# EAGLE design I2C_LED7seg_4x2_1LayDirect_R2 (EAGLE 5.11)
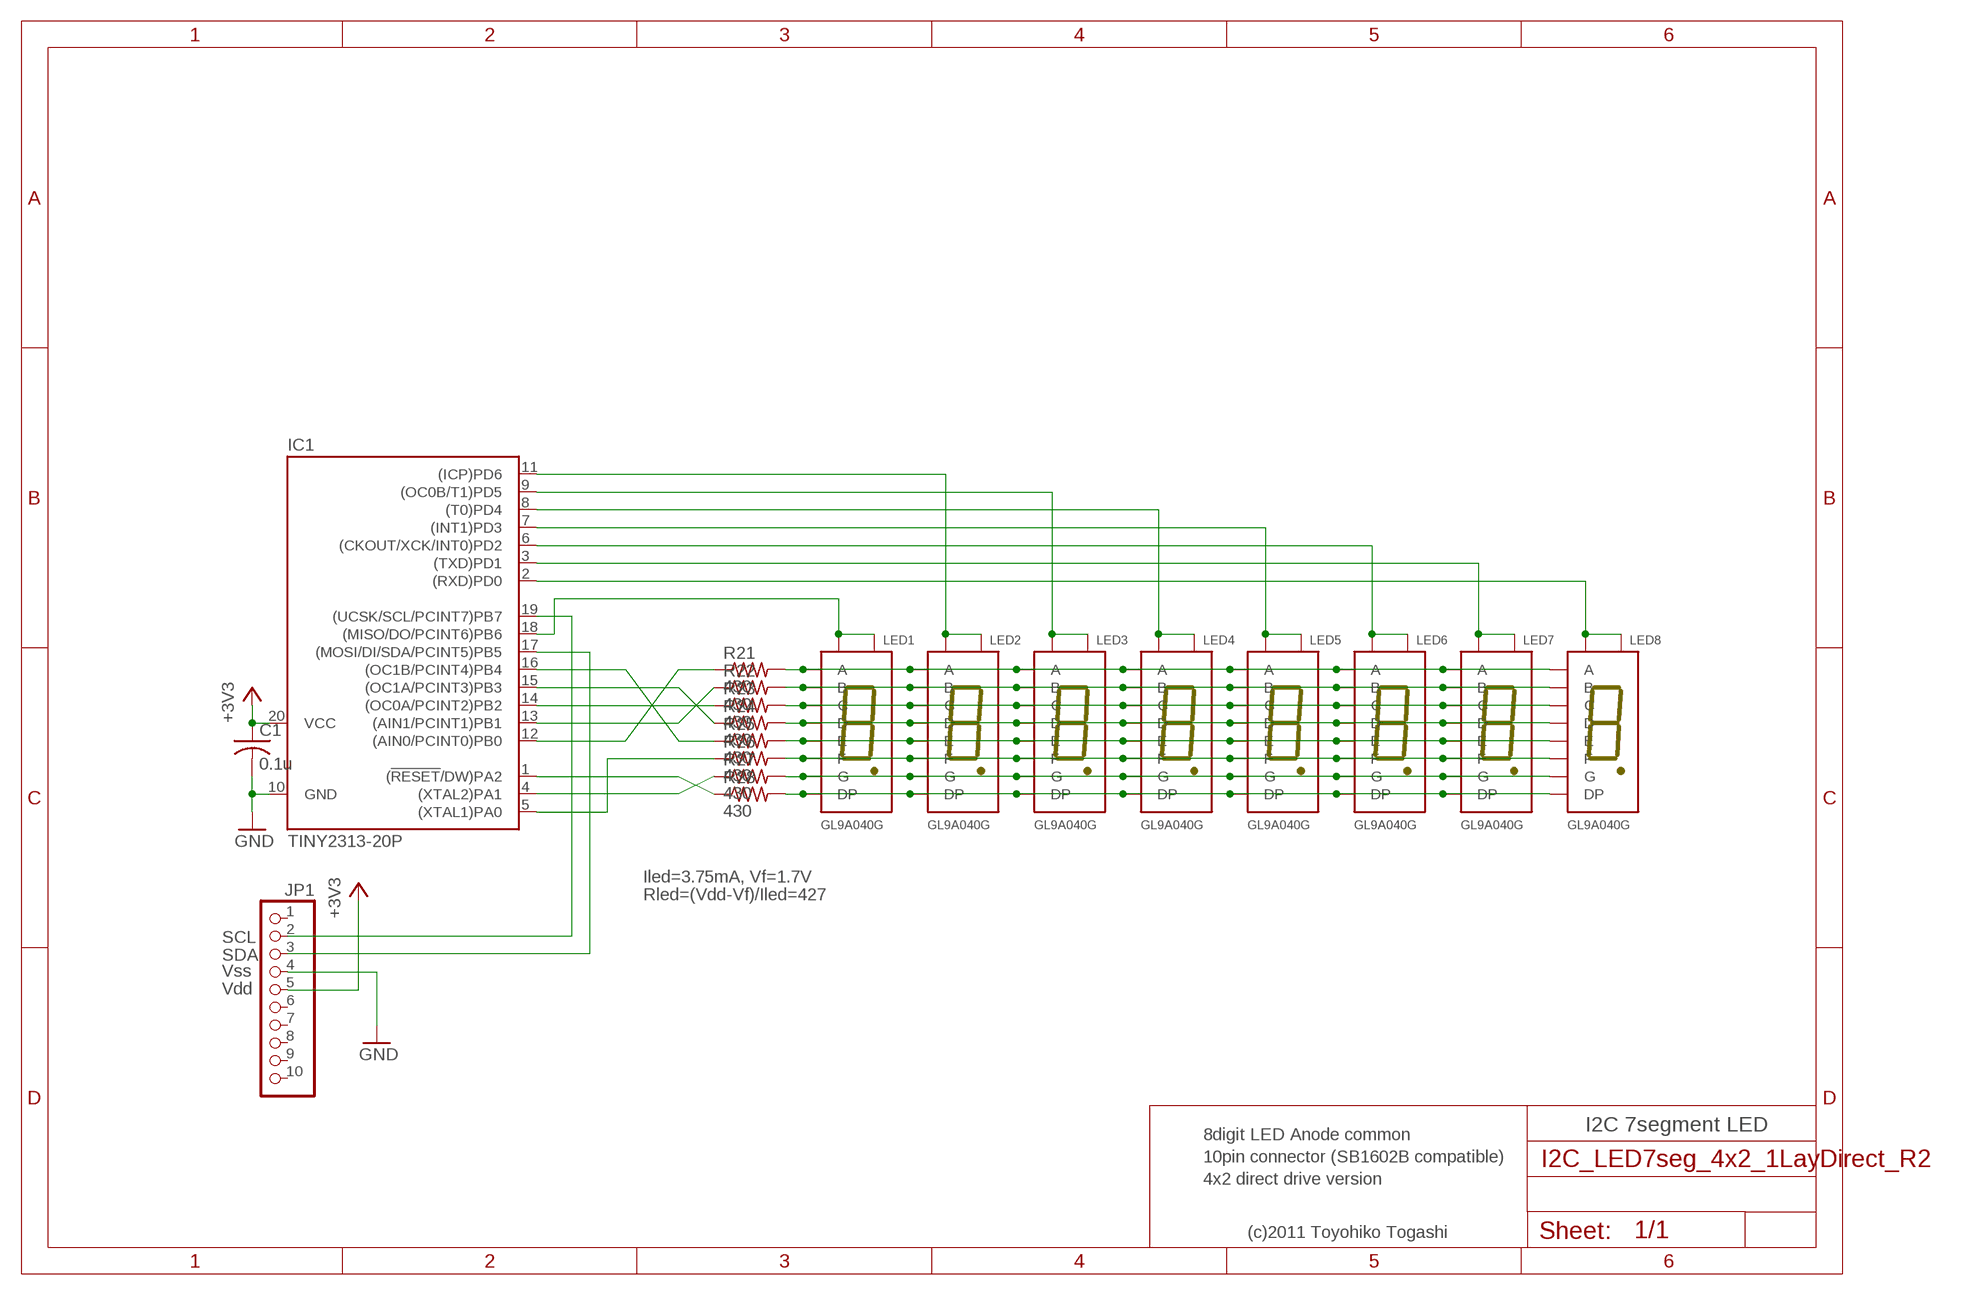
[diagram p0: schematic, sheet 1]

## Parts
C1  0.1u  C-US025-024X044  [C025-024X044]
IC1  TINY2313-20P  [DIL20]
JP1  PINHD-1X10  [1X10]
LED1  GL9A040G  [GL9A040G]
LED2  GL9A040G  [GL9A040G]
LED3  GL9A040G  [GL9A040G]
LED4  GL9A040G  [GL9A040G]
LED5  GL9A040G  [GL9A040G]
LED6  GL9A040G  [GL9A040G]
LED7  GL9A040G  [GL9A040G]
LED8  GL9A040G  [GL9A040G]
R21  430  R-US_0204/2V  [0204V]
R22  430  R-US_0204/2V  [0204V]
R23  430  R-US_0204/2V  [0204V]
R24  430  R-US_0204/2V  [0204V]
R25  430  R-US_0204/2V  [0204V]
R26  430  R-US_0204/5  [0204/5]
R27  430  R-US_0204/5  [0204/5]
R28  430  R-US_0204/5  [0204/5]

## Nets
+3V3: C1.1 IC1.20(VCC) JP1.5
GND: C1.2 IC1.10(GND) JP1.4
N$1: LED1.P$3(G) LED2.P$3(G) LED3.P$3(G) LED4.P$3(G) LED5.P$3(G) LED6.P$3(G) LED7.P$3(G) LED8.P$3(G) R27.2
N$2: LED1.P$7(DP) LED2.P$7(DP) LED3.P$7(DP) LED4.P$7(DP) LED5.P$7(DP) LED6.P$7(DP) LED7.P$7(DP) LED8.P$7(DP) R28.2
N$3: IC1.19((UCSK/SCL/PCINT7)PB7) JP1.2
N$4: IC1.17((MOSI/DI/SDA/PCINT5)PB5) JP1.3
N$5: LED1.P$10(A) LED2.P$10(A) LED3.P$10(A) LED4.P$10(A) LED5.P$10(A) LED6.P$10(A) LED7.P$10(A) LED8.P$10(A) R21.2
N$7: LED1.P$8(C) LED2.P$8(C) LED3.P$8(C) LED4.P$8(C) LED5.P$8(C) LED6.P$8(C) LED7.P$8(C) LED8.P$8(C) R23.2
N$8: LED1.P$5(D) LED2.P$5(D) LED3.P$5(D) LED4.P$5(D) LED5.P$5(D) LED6.P$5(D) LED7.P$5(D) LED8.P$5(D) R24.2
N$14: IC1.5((XTAL1)PA0) R26.1
N$15: IC1.4((XTAL2)PA1) R27.1
N$16: IC1.1((!RESET!/DW)PA2) R28.1
N$17: IC1.12((AIN0/PCINT0)PB0) R21.1
N$19: IC1.13((AIN1/PCINT1)PB1) R22.1
N$20: IC1.14((OC0A/PCINT2)PB2) R23.1
N$21: IC1.15((OC1A/PCINT3)PB3) R24.1
N$22: IC1.16((OC1B/PCINT4)PB4) R25.1
N$25: IC1.18((MISO/DO/PCINT6)PB6) LED1.P$1(CA1) LED1.P$6(CA6)
N$28: IC1.2((RXD)PD0) LED8.P$1(CA1) LED8.P$6(CA6)
N$41: LED1.P$9(B) LED2.P$9(B) LED3.P$9(B) LED4.P$9(B) LED5.P$9(B) LED6.P$9(B) LED7.P$9(B) LED8.P$9(B) R22.2
N$44: LED1.P$4(E) LED2.P$4(E) LED3.P$4(E) LED4.P$4(E) LED5.P$4(E) LED6.P$4(E) LED7.P$4(E) LED8.P$4(E) R25.2
N$45: LED1.P$2(F) LED2.P$2(F) LED3.P$2(F) LED4.P$2(F) LED5.P$2(F) LED6.P$2(F) LED7.P$2(F) LED8.P$2(F) R26.2
N$50: IC1.3((TXD)PD1) LED7.P$1(CA1) LED7.P$6(CA6)
N$53: IC1.7((INT1)PD3) LED5.P$1(CA1) LED5.P$6(CA6)
N$54: IC1.9((OC0B/T1)PD5) LED3.P$1(CA1) LED3.P$6(CA6)
N$98: IC1.11((ICP)PD6) LED2.P$1(CA1) LED2.P$6(CA6)
N$100: IC1.8((T0)PD4) LED4.P$1(CA1) LED4.P$6(CA6)
N$102: IC1.6((CKOUT/XCK/INT0)PD2) LED6.P$1(CA1) LED6.P$6(CA6)
Unconnected: JP1.1 JP1.6 JP1.7 JP1.8 JP1.9 JP1.10

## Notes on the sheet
- Iled=3.75mA, Vf=1.7V
- Rled=(Vdd-Vf)/Iled=427
- SCL
- SDA
- Vss
- Vdd
- I2C 7segment LED
- 8digit LED Anode common
- 10pin connector (SB1602B compatible)
- 4x2 direct drive version
- (c)2011 Toyohiko Togashi

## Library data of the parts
C1 = rcl:C-US: CAPACITOR, American symbol
IC1 = TOG:TINY2313: 8-bit AVR Microcontroller with 2K Bytes Flash Source: http://www.atmel.com .. doc2543.pdf
JP1 = pinhead:PINHD-1X10: PIN HEADER
LED1-LED8 = TOG:GL9A040G: 7 Segment LED
R21-R28 = rcl:R-US_: RESISTOR, American symbol

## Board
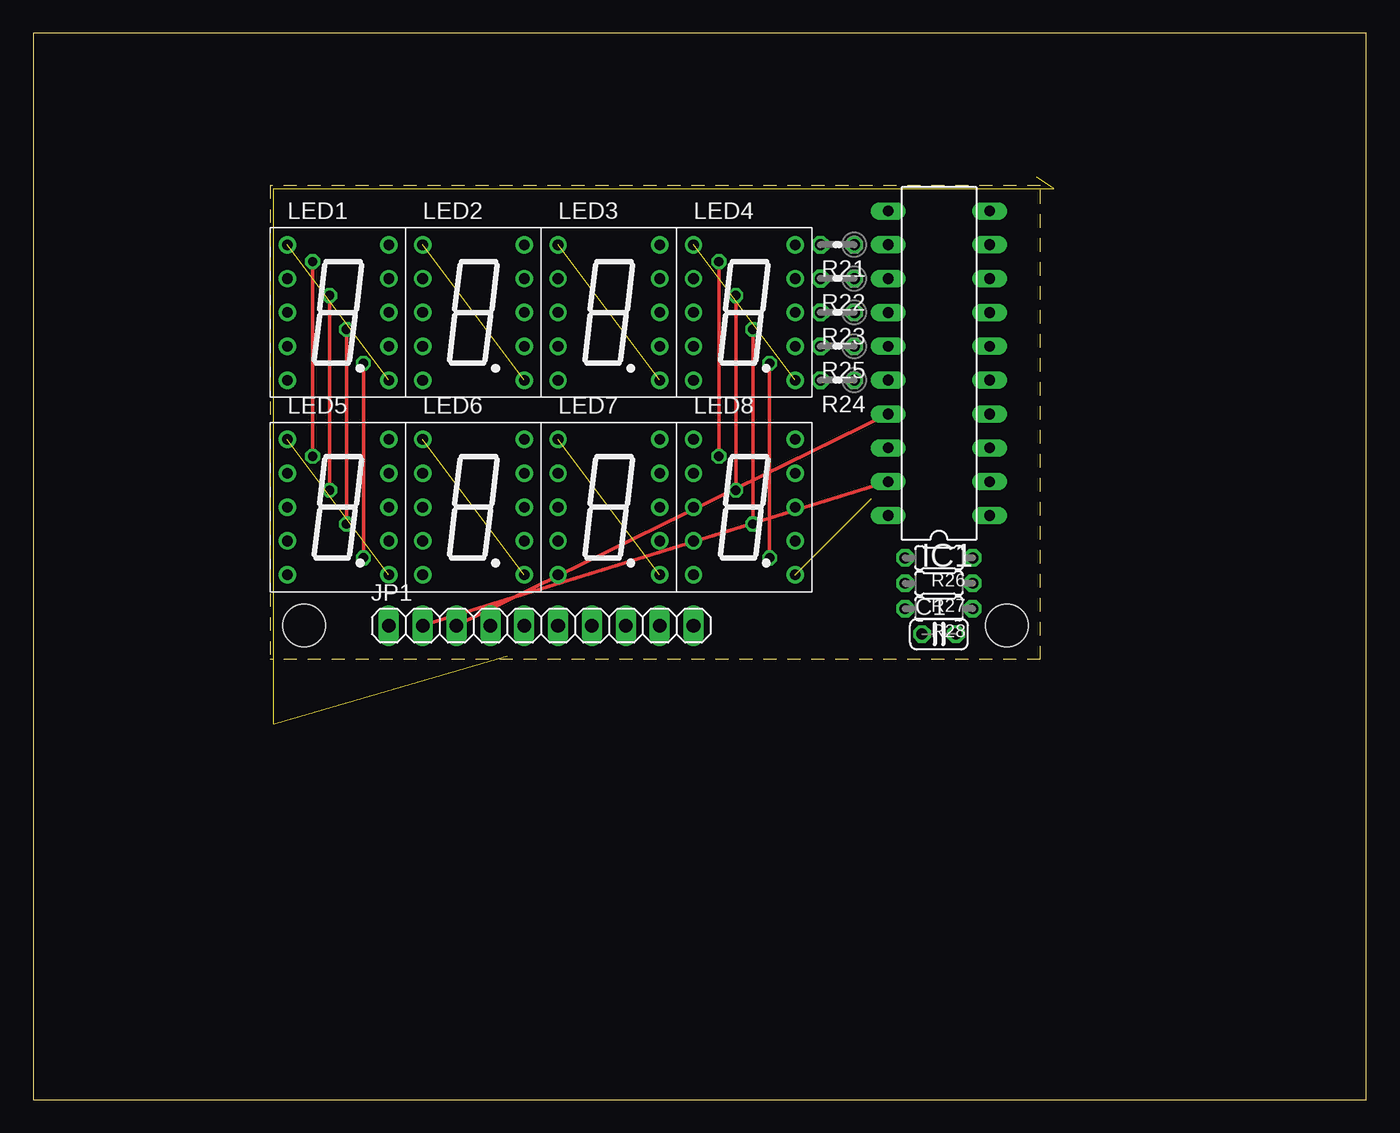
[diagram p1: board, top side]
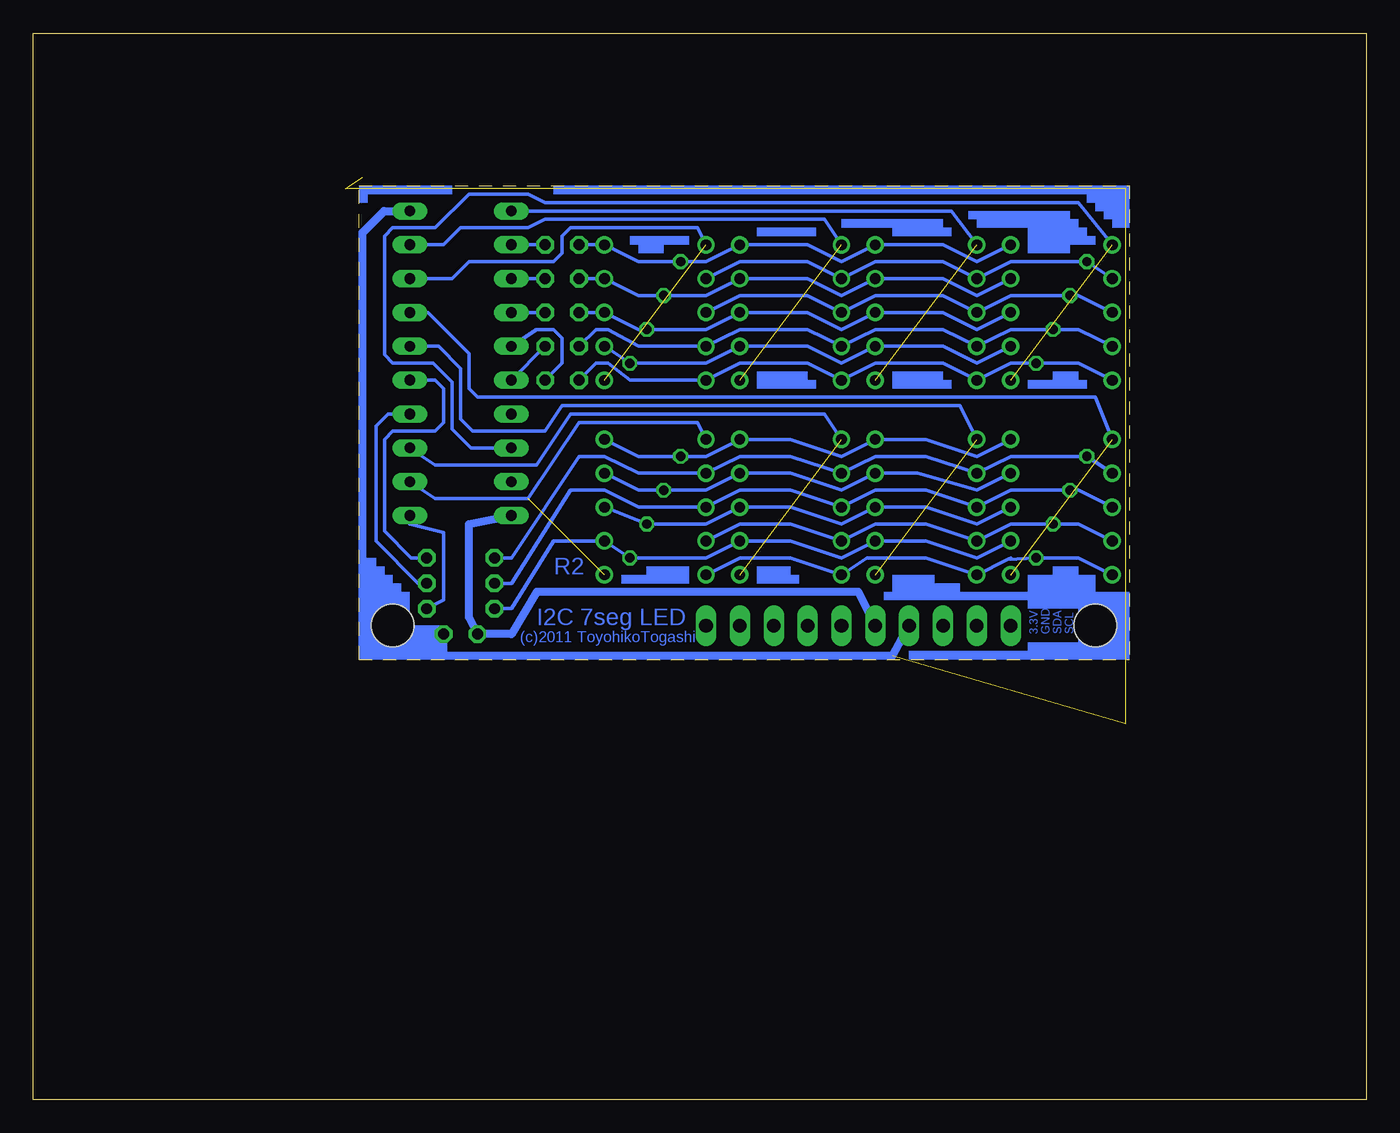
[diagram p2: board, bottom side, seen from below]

Size 100 x 80 mm. Coordinates in mm from the lower left corner, seen from the top.
Outline: 0,0 100,0 100,80 0,80 0,0
Outline: 17.78,68.58 17.78,33.02 75.56,33.02 75.56,68.58 17.78,68.58
Copper layers (1*16): Top 0.035mm / dielectric 1.5mm / Bottom 0.035mm
Design rules "default": minimum track width 10mil, minimum drill 24mil, track to track 8mil, track to pad 8mil, pad to pad 8mil, via to via 8mil, smd to smd 8mil, copper to edge 40mil, drill to drill 8mil, minimum pad ring 10mil, minimum via ring 8mil, stop-mask expansion 4mil, vias tented up to drill 0mil, thermal gap 10mil
Holes 3.2 mm at 73.03,35.56 20.32,35.56

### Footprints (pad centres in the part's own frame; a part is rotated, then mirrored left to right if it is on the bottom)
C025-024X044 = drill 0.813 octagon: 1 -1.27,0; 2 1.27,0
DIL20@1 = drill 0.813 long: 1 -11.43,-3.81; 2 -8.89,-3.81; 3 -6.35,-3.81; 4 -3.81,-3.81; 5 -1.27,-3.81; 6 1.27,-3.81; 7 3.81,-3.81; 8 6.35,-3.81; 9 8.89,-3.81; 10 11.43,-3.81; 11 11.43,3.81; 12 8.89,3.81; 13 6.35,3.81; 14 3.81,3.81; 15 1.27,3.81; 16 -1.27,3.81; 17 -3.81,3.81; 18 -6.35,3.81; 19 -8.89,3.81; 20 -11.43,3.81
1X10 = drill 1.016 long: 1 -11.43,0; 2 -8.89,0; 3 -6.35,0; 4 -3.81,0; 5 -1.27,0; 6 1.27,0; 7 3.81,0; 8 6.35,0; 9 8.89,0; 10 11.43,0
GL9A040G = drill 0.8 round: P$1 -3.81,5.08; P$2 -3.81,2.54; P$3 -3.81,0; P$4 -3.81,-2.54; P$5 -3.81,-5.08; P$6 3.81,-5.08; P$7 3.81,-2.54; P$8 3.81,0; P$9 3.81,2.54; P$10 3.81,5.08
0204V = drill 0.813 octagon: 1 -1.27,0; 2 1.27,0
0204/5 = drill 0.813 octagon: 1 -2.54,0; 2 2.54,0

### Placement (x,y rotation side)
C1  67.94,34.92 0 top
IC1  TINY2313-20P  [DIL20@1]  67.94,55.24 90 top
JP1  38.1,35.56 0 top
LED1  22.86,59.05 0 top
LED2  33.02,59.05 0 top
LED3  43.18,59.05 0 top
LED4  53.34,59.05 0 top
LED5  22.86,44.45 0 top
LED6  33.02,44.45 0 top
LED7  43.18,44.45 0 top
LED8  53.34,44.45 0 top
R21  60.33,64.14 180 top
R22  60.33,61.59 180 top
R23  60.33,59.05 180 top
R24  60.33,53.98 180 top
R25  60.33,56.52 180 top
R26  67.94,40.64 180 top
R27  67.94,38.73 180 top
R28  67.94,36.83 180 top

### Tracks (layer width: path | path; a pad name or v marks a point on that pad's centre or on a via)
+3V3
  Bottom 0.61: JP1.5 38.1,38.1 62.23,38.1 64.14,34.92 C1.1 67.31,36.2 67.31,43.18 IC1.20
GND  (4 unrouted)
  Bottom 0.61: JP1.4 35.56,33.27 69.22,33.27 | 69.22,33.27 75.31,33.27 75.31,65.05 73.69,66.67 IC1.10 | 69.22,33.27 C1.2
N$1  (via drill 0.7)
  Top 0.254: v22.23,45.72 v22.23,60.33
  Bottom 0.254: LED4.P$3 46.99,60.33 41.91,60.33 LED3.P$3 36.83,60.33 31.75,60.33 LED2.P$3 26.67,60.33 v22.23,60.33 21.59,60.33 LED1.P$3 | LED5.P$3 21.59,45.72 v22.23,45.72 26.67,45.72 LED6.P$3 33.02,45.72 36.83,45.72 LED7.P$3 43.18,45.72 46.99,45.72 LED8.P$3 54.61,44.45 57.15,45.72 59.69,45.72 64.14,38.73 R27.2
N$2  (via drill 0.7)
  Top 0.254: v55.24,40.64 v55.24,55.24
  Bottom 0.254: LED5.P$7 29.21,40.64 33.02,41.91 LED6.P$7 39.37,40.64 43.18,41.91 LED7.P$7 49.53,40.64 v55.24,40.64 LED8.P$7 60.96,41.91 64.14,36.83 R28.2 | LED1.P$7 29.21,55.24 31.75,56.52 LED2.P$7 39.37,55.24 41.91,56.52 LED3.P$7 49.53,55.24 v55.24,55.24 LED4.P$7
N$3
  Top 0.254: JP1.2 IC1.19
N$4
  Top 0.254: JP1.3 IC1.17
N$5  (via drill 0.7)
  Top 0.254: v51.44,48.26 v51.44,62.87
  Bottom 0.254: LED1.P$10 29.21,62.87 31.75,64.14 LED2.P$10 39.37,62.87 41.91,64.14 LED3.P$10 49.53,62.87 v51.44,62.87 54.61,62.87 LED4.P$10 R21.2 | LED5.P$10 29.21,48.26 33.02,49.53 LED6.P$10 39.37,48.26 43.18,49.53 LED7.P$10 49.53,48.26 v51.44,48.26 54.61,48.26 LED8.P$10
N$7  (via drill 0.7)
  Top 0.254: v53.98,43.18 v53.98,57.78
  Bottom 0.254: LED5.P$8 29.21,43.18 33.02,44.45 LED6.P$8 39.37,43.18 43.18,44.45 LED7.P$8 49.53,43.18 v53.98,43.18 LED8.P$8 | LED1.P$8 29.21,57.78 31.75,59.05 LED2.P$8 39.37,57.78 41.91,59.05 LED3.P$8 49.53,57.78 v53.98,57.78 54.61,57.78 LED4.P$8 R23.2
N$8  (via drill 0.7)
  Top 0.254: v24.77,40.64 v24.77,55.24
  Bottom 0.254: LED8.P$5 46.99,40.64 43.18,40.64 LED7.P$5 37.47,40.64 33.02,40.64 LED6.P$5 26.92,40.51 | 26.92,40.51 26.67,40.64 | LED1.P$5 21.59,55.24 v24.77,55.24 26.67,55.24 LED2.P$5 31.75,55.24 36.83,55.24 LED3.P$5 41.91,55.24 46.99,55.24 LED4.P$5 55.24,53.98 56.9,55.24 57.78,55.24 R24.2 | 26.92,40.51 v24.77,40.64 21.59,40.64 LED5.P$5
N$14
  Bottom 0.254: R26.1 71.65,40.64 73.66,42.65 73.66,49.53 73.03,50.16 69.85,50.16 69.22,50.8 69.22,53.34 69.85,53.98 IC1.5
N$15
  Bottom 0.254: R27.1 71.12,38.73 74.3,41.91 74.3,50.54 73.4,51.44 IC1.4
N$16
  Bottom 0.254: R28.1 69.22,37.47 69.22,42.55 71.75,43.18 IC1.1
N$17
  Bottom 0.254: R21.1 IC1.12
N$19
  Bottom 0.254: R22.1 IC1.13
N$20
  Bottom 0.254: R23.1 IC1.14
N$21
  Bottom 0.254: R24.1 60.33,55.24 60.33,57.15 60.96,57.78 62.23,57.78 IC1.15
N$22
  Bottom 0.254: R25.1 IC1.16
N$25  (1 unrouted)
  Bottom 0.254: LED1.P$1 21.59,67.31 61.59,67.31 62.87,67.94 67.31,67.94 69.85,65.41 73.03,65.41 73.66,64.77 73.66,55.88 73.03,55.24 70,55.24 68.58,53.83 68.58,50.31 67.16,48.9 IC1.18
N$28  (1 unrouted)
  Bottom 0.254: IC1.2 69.85,45.09 62.87,45.09 59.05,50.8 50.16,50.8 LED8.P$1
N$41  (via drill 0.7)
  Top 0.254: v52.7,45.72 v52.7,60.33
  Bottom 0.254: LED5.P$9 29.21,45.72 33.66,46.99 LED6.P$9 39.37,45.72 43.18,46.99 LED7.P$9 49.53,45.72 v52.7,45.72 54.61,45.72 LED8.P$9 | LED1.P$9 29.21,60.33 31.75,61.59 LED2.P$9 39.37,60.33 41.91,61.59 LED3.P$9 49.53,60.33 v52.7,60.33 54.61,60.33 LED4.P$9 R22.2
N$44  (via drill 0.7)
  Top 0.254: v23.5,43.18 v23.5,57.78
  Bottom 0.254: LED8.P$4 46.99,43.18 43.18,43.18 LED7.P$4 36.83,43.18 33.02,43.18 LED6.P$4 26.67,43.18 v23.5,43.18 21.59,43.18 LED5.P$4 | LED1.P$4 21.59,57.78 v23.5,57.78 26.67,57.78 LED2.P$4 31.75,57.78 36.83,57.78 LED3.P$4 41.91,57.78 46.99,57.78 LED4.P$4 54.61,56.52 56.9,57.78 57.78,57.78 R25.2
N$45  (via drill 0.7)
  Top 0.254: v20.95,48.26 v20.95,62.87
  Bottom 0.254: LED4.P$2 46.99,62.87 41.91,62.87 LED3.P$2 36.83,62.87 31.75,62.87 LED2.P$2 26.67,62.87 v20.95,62.87 LED1.P$2 | LED5.P$2 v20.95,48.26 26.67,48.26 LED6.P$2 33.02,48.26 36.83,48.26 LED7.P$2 43.18,48.26 46.99,48.26 LED8.P$2 54.61,46.99 57.15,48.26 59.05,48.26 64.14,40.64 R26.2
N$50  (1 unrouted)
  Bottom 0.254: LED7.P$1 40.64,51.44 59.69,51.44 62.23,47.62 69.85,47.62 IC1.3
N$53  (1 unrouted)
  Bottom 0.254: IC1.7 70.38,59.05 67.31,55.99 67.31,53.34 66.67,52.7 20.32,52.7 LED5.P$1
N$54  (1 unrouted)
  Bottom 0.254: LED3.P$1 40.64,66.04 61.59,66.04 62.87,65.41 67.94,65.41 69.22,64.14 IC1.9
N$98  (1 unrouted)
  Bottom 0.254: LED2.P$1 31.11,66.67 IC1.11
N$100  (1 unrouted)
  Bottom 0.254: IC1.8 68.58,61.59 67.31,62.87 60.96,62.87 60.33,63.5 60.33,64.77 59.69,65.41 50.16,65.41 LED4.P$1
N$102  (1 unrouted)
  Bottom 0.254: IC1.6 69.6,56.52 67.94,54.86 67.94,51.06 67.05,50.16 61.59,50.16 60.33,52.07 30.48,52.07 LED6.P$1
(copper drawn outside any net)
  shapes: Bottom area x51

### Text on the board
Bottom: R2 | I2C 7seg LED | SCL | SDA | GND | 3.3V | (c)2011 ToyohikoTogashi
